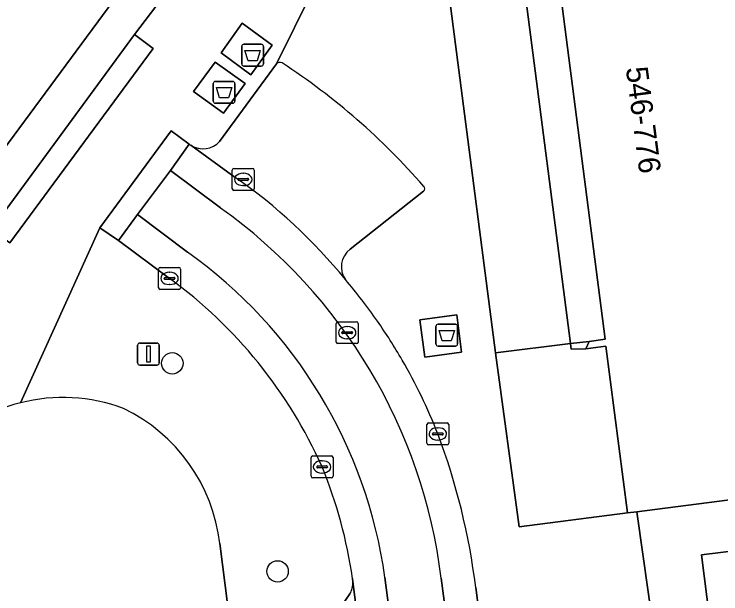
# Model space of a CAD drawing. Extents: x 160554 to 161248, y 385329 to 386506.
# Drawn here: x 161049.9 to 161082.15, y 386074.38 to 386100.85 of the extents above; entities that cross this region are included whole.
import ezdxf

# ---------------------------------------------------------------- set-up
doc = ezdxf.new("R2010")
doc.units = 0
for name, color, linetype in [('IMGEO_Afval_apart_plaats', 7, 'Continuous'), ('IMGEO_Boom', 7, 'Continuous'), ('IMGEO_Erf', 7, 'Continuous'), ('IMGEO_Groenvoorziening', 7, 'Continuous'), ('IMGEO_Kolk', 7, 'Continuous'), ('IMGEO_Lichtmast', 7, 'Continuous'), ('IMGEO_Pand', 7, 'Continuous'), ('IMGEO_Pand_nummerreeks', 7, 'Continuous'), ('IMGEO_Pand_overbouw', 7, 'Continuous'), ('IMGEO_Parkeervlak_open', 7, 'Continuous'), ('IMGEO_Rijbaan_lokaal_gesloten', 7, 'Continuous'), ('IMGEO_Rijbaan_lokaal_open', 7, 'Continuous'), ('IMGEO_Rioolput', 7, 'Continuous'), ('IMGEO_Voetpad_gesloten', 7, 'Continuous'), ('IMGEO_Voetpad_open', 7, 'Continuous')]:
    doc.layers.add(name, color=color, linetype=linetype)

msp = doc.modelspace()

# ---------------------------------------------------------------- linework, layer by layer
at = {"layer": 'IMGEO_Afval_apart_plaats'}
for p, q in [((161060.283, 386098.573), (161060.283, 386099.373)), ((161060.283, 386099.373), (161060.283, 386098.573)), ((161060.383, 386099.473), (161061.173, 386099.473)), ((161061.173, 386099.473), (161060.383, 386099.473)), ((161061.273, 386099.373), (161061.273, 386098.573)), ((161061.273, 386098.573), (161061.273, 386099.373)), ((161061.173, 386098.473), (161060.383, 386098.473)), ((161060.383, 386098.473), (161061.173, 386098.473)), ((161058.984, 386096.876), (161058.984, 386097.676)), ((161058.984, 386097.676), (161058.984, 386096.876)), ((161059.084, 386097.776), (161059.874, 386097.776)), ((161059.874, 386097.776), (161059.084, 386097.776)), ((161059.974, 386097.676), (161059.974, 386096.876)), ((161059.974, 386096.876), (161059.974, 386097.676)), ((161059.874, 386096.776), (161059.084, 386096.776)), ((161059.084, 386096.776), (161059.874, 386096.776)), ((161069.245, 386086.693), (161070.035, 386086.693)), ((161070.035, 386086.693), (161069.245, 386086.693)), ((161069.145, 386085.793), (161069.145, 386086.593)), ((161069.145, 386086.593), (161069.145, 386085.793)), ((161070.135, 386086.593), (161070.135, 386085.793)), ((161070.135, 386085.793), (161070.135, 386086.593)), ((161070.035, 386085.693), (161069.245, 386085.693)), ((161069.245, 386085.693), (161070.035, 386085.693))]:
    msp.add_line(p, q, dxfattribs=at)
for points in [[(161060.426, 386099.187), (161061.13, 386099.187), (161060.981, 386098.717), (161060.575, 386098.717), (161060.426, 386099.187)], [(161059.127, 386097.49), (161059.831, 386097.49), (161059.682, 386097.02), (161059.276, 386097.02), (161059.127, 386097.49)], [(161069.288, 386086.407), (161069.992, 386086.407), (161069.843, 386085.937), (161069.437, 386085.937), (161069.288, 386086.407)]]:
    msp.add_lwpolyline(points, dxfattribs=at)
for centre, start, end in [((161060.383, 386099.373), 90, 180), ((161060.383, 386099.373), 90, 180), ((161061.173, 386099.373), 0, 90), ((161061.173, 386099.373), 360, 90), ((161060.383, 386098.573), 180, 270), ((161060.383, 386098.573), 180, 270), ((161061.173, 386098.573), 270, 0), ((161061.173, 386098.573), 270, 0), ((161059.084, 386097.676), 90, 180), ((161059.084, 386097.676), 90, 180), ((161059.874, 386097.676), 0, 90), ((161059.874, 386097.676), 360, 90), ((161059.084, 386096.876), 180, 270), ((161059.084, 386096.876), 180, 270), ((161059.874, 386096.876), 270, 0), ((161059.874, 386096.876), 270, 0), ((161069.245, 386086.593), 90, 180), ((161069.245, 386086.593), 90, 180), ((161070.035, 386086.593), 0, 90), ((161070.035, 386086.593), 360, 90), ((161069.245, 386085.793), 180, 270), ((161069.245, 386085.793), 180, 270), ((161070.035, 386085.793), 270, 0), ((161070.035, 386085.793), 270, 0)]:
    msp.add_arc(centre, 0.1, start, end, dxfattribs=at)
at = {"layer": 'IMGEO_Boom'}
for centre in [(161057.116, 386084.907), (161061.919, 386075.408)]:
    msp.add_circle(centre, 0.489, dxfattribs=at)
at = {"layer": 'IMGEO_Erf'}
msp.add_lwpolyline([(161046.183, 386080.614), (161042.702, 386075.83), (161049.431, 386071.042), (161047.739, 386068.666), (161054.243, 386064.034), (161054.496, 386064.389), (161055.726, 386063.513), (161057.069, 386065.399), (161061.087, 386062.538), (161059.284, 386076.675)], dxfattribs=at)
for centre, radius, start, end in [((161052.138, 386075.487), 7.86, 69.5364, 104.4022), ((161052.135, 386075.498), 7.849, 104.4024, 139.3195), ((161051.47, 386075.765), 7.867, 6.6455, 64.2647)]:
    msp.add_arc(centre, radius, start, end, dxfattribs=at)
at = {"layer": 'IMGEO_Groenvoorziening'}
msp.add_lwpolyline([(161076.901, 386085.684), (161075.982, 386085.573), (161075.321, 386085.551), (161075.288, 386085.804), (161071.858, 386085.384), (161072.949, 386077.442), (161077.881, 386078.078)], close=True, dxfattribs=at)
for points in [[(161086.555, 386079.196), (161078.317, 386078.134), (161079.106, 386072.535)], [(161081.857, 386071.497), (161081.264, 386076.158), (161083.748, 386076.474), (161084.336, 386071.84)]]:
    msp.add_lwpolyline(points, dxfattribs=at)
at = {"layer": 'IMGEO_Kolk'}
for p, q in [((161059.929, 386093.802), (161060.781, 386093.802)), ((161059.854, 386092.876), (161059.854, 386093.728)), ((161060.342, 386093.582), (161060.367, 386093.582)), ((161060.855, 386093.728), (161060.855, 386092.876)), ((161060.113, 386093.296), (161060.113, 386093.308)), ((161060.551, 386093.259), (161060.153, 386093.259)), ((161060.156, 386093.345), (161060.554, 386093.345)), ((161060.597, 386093.308), (161060.597, 386093.296)), ((161060.781, 386092.802), (161059.929, 386092.802)), ((161060.365, 386093.022), (161060.34, 386093.022)), ((161056.564, 386089.283), (161057.416, 386089.283)), ((161056.489, 386088.357), (161056.489, 386089.209)), ((161056.977, 386089.063), (161057.002, 386089.063)), ((161057.49, 386089.209), (161057.49, 386088.357)), ((161056.748, 386088.777), (161056.748, 386088.789)), ((161057.186, 386088.74), (161056.788, 386088.74)), ((161056.791, 386088.826), (161057.189, 386088.826)), ((161057.232, 386088.789), (161057.232, 386088.777)), ((161057.416, 386088.283), (161056.564, 386088.283)), ((161057, 386088.503), (161056.975, 386088.503)), ((161068.806, 386082.183), (161069.658, 386082.183)), ((161068.731, 386081.257), (161068.731, 386082.109)), ((161069.219, 386081.963), (161069.244, 386081.963)), ((161069.732, 386082.109), (161069.732, 386081.257)), ((161068.99, 386081.677), (161068.99, 386081.689)), ((161069.428, 386081.64), (161069.03, 386081.64)), ((161069.033, 386081.726), (161069.431, 386081.726)), ((161069.474, 386081.689), (161069.474, 386081.677)), ((161069.242, 386081.403), (161069.217, 386081.403)), ((161069.658, 386081.183), (161068.806, 386081.183)), ((161063.449, 386079.752), (161063.449, 386080.604)), ((161063.524, 386080.678), (161064.376, 386080.678)), ((161064.45, 386080.604), (161064.45, 386079.752)), ((161063.751, 386080.221), (161064.149, 386080.221)), ((161063.937, 386080.458), (161063.962, 386080.458)), ((161063.708, 386080.172), (161063.708, 386080.184)), ((161064.146, 386080.135), (161063.748, 386080.135)), ((161063.96, 386079.898), (161063.935, 386079.898)), ((161064.192, 386080.184), (161064.192, 386080.172)), ((161064.376, 386079.678), (161063.524, 386079.678))]:
    msp.add_line(p, q, dxfattribs=at)
for points in [[(161059.929, 386093.802), (161060.781, 386093.802)], [(161059.854, 386092.876), (161059.854, 386093.728)], [(161060.855, 386093.728), (161060.855, 386092.876)], [(161060.781, 386092.802), (161059.929, 386092.802)], [(161056.564, 386089.283), (161057.416, 386089.283)], [(161056.489, 386088.357), (161056.489, 386089.209)], [(161057.49, 386089.209), (161057.49, 386088.357)], [(161057.416, 386088.283), (161056.564, 386088.283)], [(161068.806, 386082.183), (161069.658, 386082.183)], [(161068.731, 386081.257), (161068.731, 386082.109)], [(161069.732, 386082.109), (161069.732, 386081.257)], [(161069.658, 386081.183), (161068.806, 386081.183)], [(161063.449, 386079.752), (161063.449, 386080.604)], [(161063.524, 386080.678), (161064.376, 386080.678)], [(161064.45, 386080.604), (161064.45, 386079.752)], [(161064.376, 386079.678), (161063.524, 386079.678)]]:
    msp.add_lwpolyline(points, dxfattribs=at)
for centre, radius, start, end in [((161059.931, 386093.726), 0.0765, 91.552, 178.448), ((161059.931, 386093.726), 0.0765, 91.552, 178.448), ((161060.779, 386093.726), 0.0765, 1.552, 88.448), ((161060.779, 386093.726), 0.0765, 1.552, 88.448), ((161060.153, 386093.305), 0.0403, 85.8775, 175.7526), ((161060.15, 386093.295), 0.0366, 178.938, 274.7102), ((161060.554, 386093.302), 0.043, 264.8664, 352.4533), ((161060.558, 386093.307), 0.0386, 1.7309, 96.639), ((161059.931, 386092.878), 0.0765, 181.552, 268.448), ((161059.931, 386092.878), 0.0765, 181.552, 268.448), ((161060.779, 386092.878), 0.0765, 271.552, 358.448), ((161060.779, 386092.878), 0.0765, 271.552, 358.448), ((161056.566, 386089.207), 0.0765, 91.552, 178.448), ((161056.566, 386089.207), 0.0765, 91.552, 178.448), ((161057.414, 386089.207), 0.0765, 1.552, 88.448), ((161057.414, 386089.207), 0.0765, 1.552, 88.448), ((161056.788, 386088.786), 0.0403, 85.8775, 175.7526), ((161056.785, 386088.776), 0.0366, 178.938, 274.7102), ((161057.189, 386088.783), 0.043, 264.8664, 352.4533), ((161057.193, 386088.788), 0.0386, 1.7309, 96.639), ((161056.566, 386088.359), 0.0765, 181.552, 268.448), ((161056.566, 386088.359), 0.0765, 181.552, 268.448), ((161057.414, 386088.359), 0.0765, 271.552, 358.448), ((161057.414, 386088.359), 0.0765, 271.552, 358.448), ((161068.808, 386082.107), 0.0765, 91.552, 178.448), ((161068.808, 386082.107), 0.0765, 91.552, 178.448), ((161069.656, 386082.107), 0.0765, 1.552, 88.448), ((161069.656, 386082.107), 0.0765, 1.552, 88.448), ((161069.03, 386081.686), 0.0403, 85.8775, 175.7526), ((161069.027, 386081.676), 0.0366, 178.938, 274.7102), ((161069.431, 386081.683), 0.043, 264.8664, 352.4533), ((161069.435, 386081.688), 0.0386, 1.7309, 96.639), ((161068.808, 386081.259), 0.0765, 181.552, 268.448), ((161068.808, 386081.259), 0.0765, 181.552, 268.448), ((161069.656, 386081.259), 0.0765, 271.552, 358.448), ((161069.656, 386081.259), 0.0765, 271.552, 358.448), ((161063.526, 386080.602), 0.0765, 91.552, 178.448), ((161063.526, 386080.602), 0.0765, 91.552, 178.448), ((161064.374, 386080.602), 0.0765, 1.552, 88.448), ((161064.374, 386080.602), 0.0765, 1.552, 88.448), ((161063.748, 386080.181), 0.0403, 85.8775, 175.7526), ((161064.153, 386080.183), 0.0386, 1.7309, 96.639), ((161063.745, 386080.171), 0.0366, 178.938, 274.7102), ((161064.149, 386080.178), 0.043, 264.8664, 352.4533), ((161063.526, 386079.754), 0.0765, 181.552, 268.448), ((161063.526, 386079.754), 0.0765, 181.552, 268.448), ((161064.374, 386079.754), 0.0765, 271.552, 358.448), ((161064.374, 386079.754), 0.0765, 271.552, 358.448)]:
    msp.add_arc(centre, radius, start, end, dxfattribs=at)
for centre, major_axis, ratio, start_param, end_param in [((161060.341, 386093.302), (-0.387, 0.002), 0.722429, 4.712389, 7.853982), ((161060.366, 386093.302), (-0.39, 0.002), 0.717154, 1.570796, 4.712389), ((161056.976, 386088.783), (-0.387, 0.002), 0.722429, 4.712389, 7.853982), ((161057.001, 386088.783), (-0.39, 0.002), 0.717154, 1.570796, 4.712389), ((161069.218, 386081.683), (-0.387, 0.002), 0.722429, 4.712389, 7.853982), ((161069.243, 386081.683), (-0.39, 0.002), 0.717154, 1.570796, 4.712389), ((161063.936, 386080.178), (-0.387, 0.002), 0.722429, 4.712389, 7.853982), ((161063.961, 386080.178), (-0.39, 0.002), 0.717154, 1.570796, 4.712389)]:
    msp.add_ellipse(centre, major_axis=major_axis, ratio=ratio, start_param=start_param, end_param=end_param, dxfattribs=at)
at = {"layer": 'IMGEO_Lichtmast'}
for p, q in [((161055.533, 386084.928), (161055.533, 386085.728)), ((161055.533, 386085.728), (161055.533, 386084.928)), ((161055.633, 386085.828), (161056.423, 386085.828)), ((161056.423, 386085.828), (161055.633, 386085.828)), ((161056.523, 386085.728), (161056.523, 386084.928)), ((161056.523, 386084.928), (161056.523, 386085.728)), ((161056.423, 386084.828), (161055.633, 386084.828)), ((161055.633, 386084.828), (161056.423, 386084.828))]:
    msp.add_line(p, q, dxfattribs=at)
msp.add_lwpolyline([(161055.953, 386085.703), (161056.103, 386085.703), (161056.103, 386084.953), (161055.953, 386084.953), (161055.953, 386085.703)], dxfattribs=at)
for centre, start, end in [((161055.633, 386085.728), 90, 180), ((161055.633, 386085.728), 90, 180), ((161056.423, 386085.728), 0, 90), ((161056.423, 386085.728), 360, 90), ((161055.633, 386084.928), 180, 270), ((161055.633, 386084.928), 180, 270), ((161056.423, 386084.928), 270, 0), ((161056.423, 386084.928), 270, 0)]:
    msp.add_arc(centre, 0.1, start, end, dxfattribs=at)
at = {"layer": 'IMGEO_Pand'}
msp.add_lwpolyline([(161083.966, 386123.701), (161076.697, 386114.283), (161075.694, 386112.984), (161073.717, 386110.422), (161076.862, 386086.002), (161076.133, 386085.908), (161075.982, 386085.573), (161076.901, 386085.684), (161077.881, 386078.078), (161078.317, 386078.134), (161086.555, 386079.196)], dxfattribs=at)
at = {"layer": 'IMGEO_Pand_overbouw'}
msp.add_lwpolyline([(161076.697, 386114.283), (161075.939, 386114.886), (161074.997, 386114.731), (161074.314, 386113.855), (161072.19, 386111.129), (161072.035, 386110.93), (161073.141, 386102.388), (161075.288, 386085.804), (161075.321, 386085.551), (161075.982, 386085.573), (161076.133, 386085.908), (161076.862, 386086.002), (161073.717, 386110.422), (161075.694, 386112.984)], close=True, dxfattribs=at)
at = {"layer": 'IMGEO_Parkeervlak_open'}
for points in [[(161061.873, 386098.579), (161059.275, 386095.034)], [(161057.969, 386094.859), (161059.99, 386093.394)], [(161065.228, 386090.112), (161068.583, 386092.758)], [(161066.623, 386065.212), (161066.618, 386065.254), (161065.354, 386074.934)], [(161065.221, 386074.382), (161063.918, 386072.498)]]:
    msp.add_lwpolyline(points, dxfattribs=at)
msp.add_lwpolyline([(161084.336, 386071.84), (161083.748, 386076.474), (161081.264, 386076.158), (161081.857, 386071.497)], close=True, dxfattribs=at)
for centre, radius, start, end in [((161062.027, 386098.435), 0.211, 61.7849, 136.9934), ((161045.177, 386072.661), 31.003, 40.9629, 56.8588), ((161058.519, 386095.718), 1.02, 237.3868, 317.8772), ((161045.902, 386073.189), 24.632, 39.1174, 55.1151), ((161068.475, 386092.875), 0.159, 312.6588, 44.3263), ((161065.837, 386089.309), 1.008, 127.189, 215.1382), ((161064.375, 386074.878), 0.981, 329.6238, 3.2826)]:
    msp.add_arc(centre, radius, start, end, dxfattribs=at)
at = {"layer": 'IMGEO_Rijbaan_lokaal_gesloten'}
msp.add_lwpolyline([(161069.681, 386117.938), (161074.292, 386123.641), (161081.309, 386132.396), (161085.633, 386137.767), (161087.491, 386140.075), (161085.801, 386140.941), (161084.607, 386139.388), (161078.703, 386131.943), (161072.93, 386124.739), (161068.319, 386119.036), (161057.022, 386104.982), (161033.511, 386073.119), (161034.909, 386072.065), (161040.604, 386079.805), (161042.846, 386082.833), (161047.102, 386088.62), (161048.852, 386091.014), (161055.399, 386099.92), (161057.387, 386102.546), (161058.409, 386103.914), (161058.635, 386104.166), (161060.51, 386106.536)], close=True, dxfattribs=at)
for points in [[(161071.993, 386133.478), (161067.245, 386126.804), (161029.882, 386075.853), (161033.511, 386073.119), (161057.022, 386104.982), (161068.319, 386119.036), (161072.93, 386124.739), (161078.703, 386131.943), (161084.607, 386139.388)], [(161057.892, 386094.914), (161057.03, 386093.706), (161059.31, 386091.997)], [(161059.99, 386093.394), (161057.969, 386094.859)], [(161055.522, 386091.694), (161054.655, 386090.509), (161056.99, 386088.783)], [(161057.808, 386089.986), (161055.522, 386091.694)], [(161065.335, 386075.084), (161065.354, 386074.934), (161066.618, 386065.254), (161066.623, 386065.212), (161066.918, 386062.96), (161067.093, 386061.671), (161067.992, 386054.799), (161068.384, 386051.777), (161073.09, 386015.931), (161074.577, 386016.14), (161066.82, 386075.134)], [(161069.383, 386075.101), (161077.097, 386016.484), (161078.548, 386016.673), (161074.333, 386048.815), (161073.354, 386056.178), (161071.106, 386073.6)], [(161071.106, 386073.6), (161070.96, 386074.678)]]:
    msp.add_lwpolyline(points, dxfattribs=at)
for centre, radius, start, end in [((161058.361, 386095.489), 0.741, 230.803, 238.1216), ((161045.902, 386073.189), 24.632, 39.1174, 55.1151), ((161045.224, 386072.148), 24.339, 6.9677, 54.6371), ((161045.069, 386072.096), 21.962, 7.9509, 54.5468), ((161044.391, 386071.475), 21.407, 23.9863, 53.9478), ((161046.104, 386072.645), 24.824, 34.8561, 40.3861), ((161046.622, 386072.948), 24.226, 29.9837, 34.967), ((161046.126, 386072.619), 24.821, 21.4188, 30.0686), ((161040.825, 386070.96), 30.363, 7.0337, 20.6806), ((161044.403, 386072.128), 21.14, 8.0379, 22.3828)]:
    msp.add_arc(centre, radius, start, end, dxfattribs=at)
at = {"layer": 'IMGEO_Rijbaan_lokaal_open'}
for points in [[(161059.31, 386091.997), (161057.03, 386093.706), (161055.522, 386091.694), (161057.808, 386089.986)], [(161066.82, 386075.134), (161074.577, 386016.14), (161077.097, 386016.484), (161069.383, 386075.101)]]:
    msp.add_lwpolyline(points, dxfattribs=at)
for centre, radius, start, end in [((161045.224, 386072.148), 24.339, 6.9677, 54.6371), ((161045.069, 386072.096), 21.962, 7.9509, 54.5468)]:
    msp.add_arc(centre, radius, start, end, dxfattribs=at)
at = {"layer": 'IMGEO_Rioolput'}
for p, q in [((161064.596, 386085.879), (161064.596, 386086.731)), ((161064.671, 386086.805), (161065.523, 386086.805)), ((161065.597, 386086.731), (161065.597, 386085.879)), ((161064.898, 386086.348), (161065.296, 386086.348)), ((161065.084, 386086.585), (161065.109, 386086.585)), ((161064.855, 386086.299), (161064.855, 386086.311)), ((161065.293, 386086.262), (161064.895, 386086.262)), ((161065.107, 386086.025), (161065.082, 386086.025)), ((161065.339, 386086.311), (161065.339, 386086.299)), ((161065.523, 386085.805), (161064.671, 386085.805))]:
    msp.add_line(p, q, dxfattribs=at)
for points in [[(161064.596, 386085.879), (161064.596, 386086.731)], [(161064.671, 386086.805), (161065.523, 386086.805)], [(161065.597, 386086.731), (161065.597, 386085.879)], [(161065.523, 386085.805), (161064.671, 386085.805)]]:
    msp.add_lwpolyline(points, dxfattribs=at)
for centre, radius, start, end in [((161064.673, 386086.729), 0.0765, 91.552, 178.448), ((161064.673, 386086.729), 0.0765, 91.552, 178.448), ((161065.521, 386086.729), 0.0765, 1.552, 88.448), ((161065.521, 386086.729), 0.0765, 1.552, 88.448), ((161064.895, 386086.308), 0.0403, 85.8775, 175.7526), ((161065.3, 386086.31), 0.0386, 1.7309, 96.639), ((161064.892, 386086.298), 0.0366, 178.938, 274.7102), ((161065.296, 386086.305), 0.043, 264.8664, 352.4533), ((161064.673, 386085.881), 0.0765, 181.552, 268.448), ((161064.673, 386085.881), 0.0765, 181.552, 268.448), ((161065.521, 386085.881), 0.0765, 271.552, 358.448), ((161065.521, 386085.881), 0.0765, 271.552, 358.448)]:
    msp.add_arc(centre, radius, start, end, dxfattribs=at)
for centre, major_axis, ratio, start_param, end_param in [((161065.083, 386086.305), (-0.387, 0.002), 0.722429, 4.712389, 7.853982), ((161065.108, 386086.305), (-0.39, 0.002), 0.717154, 1.570796, 4.712389)]:
    msp.add_ellipse(centre, major_axis=major_axis, ratio=ratio, start_param=start_param, end_param=end_param, dxfattribs=at)
at = {"layer": 'IMGEO_Voetpad_gesloten'}
for points in [[(161060.311, 386100.439), (161059.34, 386099.076), (161060.701, 386098.074), (161061.678, 386099.435)], [(161060.439, 386097.68), (161059.076, 386098.658), (161058.089, 386097.311), (161059.453, 386096.326)], [(161070.098, 386087.119), (161068.416, 386086.895), (161068.639, 386085.182), (161070.313, 386085.416)]]:
    msp.add_lwpolyline(points, close=True, dxfattribs=at)
at = {"layer": 'IMGEO_Voetpad_open'}
for points in [[(161059.275, 386095.034), (161061.873, 386098.579), (161068.448, 386111.866), (161070.422, 386114.33), (161071.468, 386115.652), (161081.122, 386128.433), (161087.188, 386136.952), (161087.442, 386137.307), (161085.633, 386137.767), (161081.309, 386132.396), (161074.292, 386123.641), (161069.681, 386117.938)], [(161082.13, 386049.396), (161080.632, 386060.626), (161079.989, 386065.451), (161079.91, 386066.216), (161079.298, 386071.172), (161079.106, 386072.535), (161078.317, 386078.134), (161077.881, 386078.078), (161072.949, 386077.442), (161071.858, 386085.384), (161069.72, 386101.947), (161068.448, 386111.866), (161061.873, 386098.579)], [(161058.635, 386104.166), (161058.409, 386103.914), (161057.387, 386102.546), (161055.399, 386099.92), (161056.248, 386099.283), (161049.697, 386090.41), (161048.852, 386091.014), (161047.102, 386088.62), (161042.846, 386082.833), (161040.604, 386079.805)], [(161050.183, 386083.1), (161053.807, 386091.097), (161057.058, 386095.52), (161057.892, 386094.914)], [(161068.583, 386092.758), (161065.228, 386090.112)], [(161056.99, 386088.783), (161054.655, 386090.509), (161053.807, 386091.097), (161050.183, 386083.1)], [(161059.284, 386076.675), (161061.087, 386062.538), (161061.384, 386060.454), (161061.741, 386057.757), (161063.757, 386042.459), (161064.4, 386037.651), (161065.063, 386032.642), (161069.382, 386000), (161073.924, 385966.182), (161074.387, 385962.734), (161074.404, 385962.606), (161074.645, 385960.809), (161077.722, 385937.898)], [(161065.354, 386074.934), (161065.335, 386075.084)], [(161070.96, 386074.678), (161071.106, 386073.6)], [(161063.918, 386072.498), (161065.221, 386074.382)]]:
    msp.add_lwpolyline(points, dxfattribs=at)
for points in [[(161071.943, 386113.104), (161070.422, 386114.33), (161068.448, 386111.866), (161069.72, 386101.947), (161071.858, 386085.384), (161075.288, 386085.804), (161073.141, 386102.388), (161072.035, 386110.93), (161072.19, 386111.129)], [(161075.288, 386085.804), (161076.133, 386085.908), (161076.862, 386086.002), (161073.717, 386110.422), (161075.694, 386112.984), (161074.314, 386113.855), (161072.19, 386111.129), (161073.28, 386102.406), (161073.141, 386102.388)], [(161060.311, 386100.439), (161061.678, 386099.435), (161060.701, 386098.074), (161059.34, 386099.076)], [(161055.399, 386099.92), (161048.852, 386091.014), (161049.697, 386090.41), (161056.248, 386099.283)], [(161058.089, 386097.311), (161059.076, 386098.658), (161060.439, 386097.68), (161059.453, 386096.326)], [(161057.03, 386093.706), (161057.892, 386094.914), (161057.058, 386095.52), (161053.807, 386091.097), (161054.655, 386090.509), (161055.522, 386091.694)], [(161068.639, 386085.182), (161068.416, 386086.895), (161070.098, 386087.119), (161070.313, 386085.416)], [(161075.982, 386085.573), (161076.133, 386085.908), (161075.288, 386085.804), (161075.321, 386085.551)]]:
    msp.add_lwpolyline(points, close=True, dxfattribs=at)
for centre, radius, start, end in [((161062.027, 386098.435), 0.211, 61.7849, 136.9934), ((161045.177, 386072.661), 31.003, 40.9629, 56.8588), ((161058.361, 386095.489), 0.741, 230.803, 238.1216), ((161058.519, 386095.718), 1.02, 237.3868, 317.8772), ((161068.475, 386092.875), 0.159, 312.6588, 44.3263), ((161065.837, 386089.309), 1.008, 127.189, 215.1382), ((161044.391, 386071.475), 21.407, 23.9863, 53.9478), ((161046.104, 386072.645), 24.824, 34.8561, 40.3861), ((161046.622, 386072.948), 24.226, 29.9837, 34.967), ((161046.126, 386072.619), 24.821, 21.4188, 30.0686), ((161052.138, 386075.487), 7.86, 69.5364, 104.4022), ((161052.135, 386075.498), 7.849, 104.4024, 139.3195), ((161051.47, 386075.765), 7.867, 6.6455, 64.2647), ((161040.825, 386070.96), 30.363, 7.0337, 20.6806), ((161044.403, 386072.128), 21.14, 8.0379, 22.3828), ((161064.375, 386074.878), 0.981, 329.6238, 3.2826)]:
    msp.add_arc(centre, radius, start, end, dxfattribs=at)

# ---------------------------------------------------------------- texts
at = {"layer": 'IMGEO_Pand_nummerreeks'}
msp.add_text('546-776', height=1, rotation=277.3336, dxfattribs=at).set_placement((161077.807, 386098.389))

doc.saveas('drawing.dxf')
